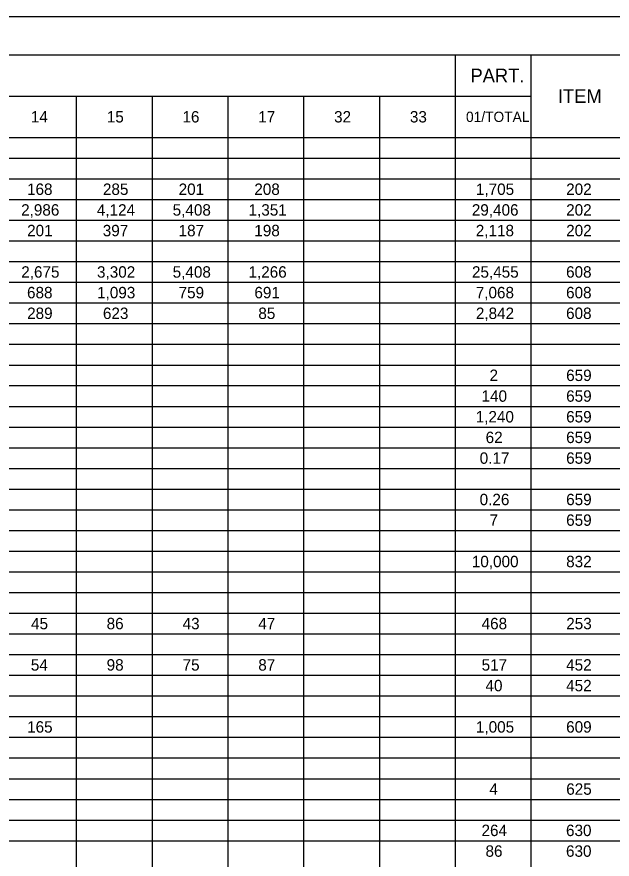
# Model space of a CAD drawing. Extents: x 0 to 34, y 0 to 22.
# Drawn here: x 9.02 to 16.86, y 10.89 to 22 of the extents above; entities that cross this region are included whole.
import ezdxf

# ---------------------------------------------------------------- set-up
doc = ezdxf.new("R2010")
doc.units = 0
for name, color, linetype in [('Default', 7, 'Continuous'), ('SH_Border', 7, 'Continuous'), ('SH_Cut_Line', 7, 'Continuous')]:
    doc.layers.add(name, color=color, linetype=linetype)

msp = doc.modelspace()

# ---------------------------------------------------------------- linework, layer by layer
at = {"layer": 'Default'}
for p, q in [((1.5, 21.5), (31.993, 21.5)), ((14.791, 21.5), (14.791, 1.047)), ((15.79, 21.5), (15.79, 1.047)), ((1.5, 20.955), (15.79, 20.955)), ((9.799, 20.955), (9.799, 1.047)), ((10.798, 20.955), (10.798, 1.047)), ((11.796, 20.955), (11.796, 1.047)), ((12.794, 20.955), (12.794, 1.047)), ((13.793, 20.955), (13.793, 1.047)), ((1.5, 20.409), (31.993, 20.409)), ((1.5, 20.136), (31.993, 20.136)), ((1.5, 19.864), (31.993, 19.864)), ((1.5, 19.591), (31.993, 19.591)), ((1.5, 19.318), (31.993, 19.318)), ((1.5, 19.046), (31.993, 19.046)), ((1.5, 18.773), (31.993, 18.773)), ((1.5, 18.5), (31.993, 18.5)), ((1.5, 18.227), (31.993, 18.227)), ((1.5, 17.955), (31.993, 17.955)), ((1.5, 17.682), (31.993, 17.682)), ((1.5, 17.409), (31.993, 17.409)), ((1.5, 17.137), (31.993, 17.137)), ((1.5, 16.864), (31.993, 16.864)), ((1.5, 16.591), (31.993, 16.591)), ((1.5, 16.318), (31.993, 16.318)), ((1.5, 16.046), (31.993, 16.046)), ((1.5, 15.773), (31.993, 15.773)), ((1.5, 15.5), (31.993, 15.5)), ((1.5, 15.228), (31.993, 15.228)), ((1.5, 14.955), (31.993, 14.955)), ((1.5, 14.682), (31.993, 14.682)), ((1.5, 14.41), (31.993, 14.41)), ((1.5, 14.137), (31.993, 14.137)), ((1.5, 13.864), (31.993, 13.864)), ((1.5, 13.591), (31.993, 13.591)), ((1.5, 13.319), (31.993, 13.319)), ((1.5, 13.046), (31.993, 13.046)), ((1.5, 12.773), (31.993, 12.773)), ((1.5, 12.501), (31.993, 12.501)), ((1.5, 12.228), (31.993, 12.228)), ((1.5, 11.955), (31.993, 11.955)), ((1.5, 11.682), (31.993, 11.682)), ((1.5, 11.41), (31.993, 11.41)), ((1.5, 11.137), (31.993, 11.137))]:
    msp.add_line(p, q, dxfattribs=at)
at = {"layer": 'SH_Border'}
msp.add_lwpolyline([(1.5, 21.5), (33.5, 21.5), (33.5, 0.5), (1.5, 0.5)], close=True, dxfattribs=at)
at = {"layer": 'SH_Cut_Line'}
msp.add_lwpolyline([(0, 0), (34, 0), (34, 22), (0, 22)], close=True, dxfattribs=at)

# ---------------------------------------------------------------- texts
at = {"layer": 'Default'}
for s, height, p in [('PART.', 0.1806, (14.993, 21.137)), ('ITEM', 0.1806, (16.146, 20.864)), ('14', 0.1505, (9.2, 20.607)), ('15', 0.1505, (10.201, 20.607)), ('16', 0.1505, (11.198, 20.607)), ('17', 0.1505, (12.197, 20.607)), ('32', 0.1505, (13.196, 20.607)), ('33', 0.1505, (14.195, 20.607)), ('01/TOTAL', 0.1355, (14.934, 20.614)), ('168', 0.1505, (9.15, 19.652)), ('285', 0.1505, (10.15, 19.652)), ('201', 0.1505, (11.148, 19.652)), ('208', 0.1505, (12.145, 19.652)), ('1,705', 0.1505, (15.065, 19.652)), ('202', 0.1505, (16.254, 19.652)), ('2,986', 0.1505, (9.072, 19.379)), ('4,124', 0.1505, (10.07, 19.379)), ('5,408', 0.1505, (11.069, 19.379)), ('1,351', 0.1505, (12.069, 19.379)), ('29,406', 0.1505, (15.011, 19.379)), ('202', 0.1505, (16.254, 19.379)), ('201', 0.1505, (9.151, 19.107)), ('397', 0.1505, (10.148, 19.107)), ('187', 0.1505, (11.147, 19.107)), ('198', 0.1505, (12.145, 19.107)), ('2,118', 0.1505, (15.063, 19.107)), ('202', 0.1505, (16.254, 19.107)), ('2,675', 0.1505, (9.074, 18.561)), ('3,302', 0.1505, (10.072, 18.561)), ('5,408', 0.1505, (11.069, 18.561)), ('1,266', 0.1505, (12.068, 18.561)), ('25,455', 0.1505, (15.013, 18.561)), ('608', 0.1505, (16.253, 18.561)), ('688', 0.1505, (9.15, 18.289)), ('1,093', 0.1505, (10.073, 18.289)), ('759', 0.1505, (11.147, 18.289)), ('691', 0.1505, (12.146, 18.289)), ('7,068', 0.1505, (15.063, 18.289)), ('608', 0.1505, (16.253, 18.289)), ('289', 0.1505, (9.151, 18.016)), ('623', 0.1505, (10.15, 18.016)), ('85', 0.1505, (12.198, 18.016)), ('2,842', 0.1505, (15.064, 18.016)), ('608', 0.1505, (16.253, 18.016)), ('2', 0.151, (15.244, 17.198)), ('659', 0.1505, (16.254, 17.198)), ('140', 0.1505, (15.139, 16.925)), ('659', 0.1505, (16.254, 16.925)), ('1,240', 0.1505, (15.062, 16.652)), ('659', 0.1505, (16.254, 16.652)), ('62', 0.1505, (15.193, 16.38)), ('659', 0.1505, (16.254, 16.38)), ('0.17', 0.1505, (15.115, 16.107)), ('659', 0.1505, (16.254, 16.107)), ('0.26', 0.1505, (15.114, 15.561)), ('659', 0.1505, (16.254, 15.561)), ('7', 0.151, (15.244, 15.289)), ('659', 0.1505, (16.254, 15.289)), ('10,000', 0.1505, (15.011, 14.743)), ('832', 0.1505, (16.254, 14.743)), ('45', 0.1505, (9.203, 13.925)), ('86', 0.1505, (10.199, 13.925)), ('43', 0.1505, (11.2, 13.925)), ('47', 0.1505, (12.197, 13.925)), ('468', 0.1505, (15.14, 13.925)), ('253', 0.1505, (16.255, 13.925)), ('54', 0.1505, (9.2, 13.38)), ('98', 0.1505, (10.199, 13.38)), ('75', 0.1505, (11.2, 13.38)), ('87', 0.1505, (12.197, 13.38)), ('517', 0.1505, (15.14, 13.38)), ('452', 0.1505, (16.254, 13.38)), ('40', 0.1505, (15.191, 13.107)), ('452', 0.1505, (16.254, 13.107)), ('165', 0.1505, (9.151, 12.562)), ('1,005', 0.1505, (15.065, 12.562)), ('609', 0.1505, (16.254, 12.562)), ('4', 0.151, (15.242, 11.743)), ('625', 0.1505, (16.255, 11.743)), ('264', 0.1505, (15.139, 11.198)), ('630', 0.1505, (16.252, 11.198)), ('86', 0.1505, (15.191, 10.925)), ('630', 0.1505, (16.252, 10.925))]:
    msp.add_text(s, height=height, dxfattribs=at).set_placement(p)

doc.saveas('drawing.dxf')
